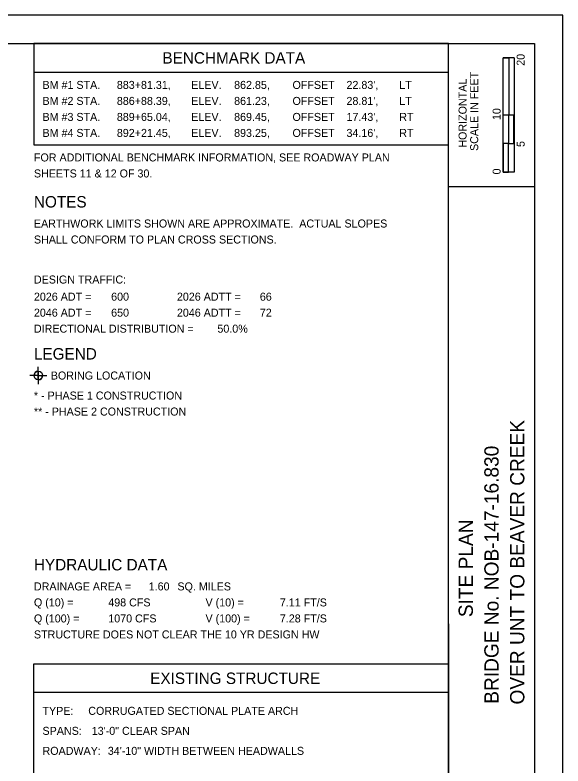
# Model space of a CAD drawing. Extents: x 0 to 2765, y 0 to 220.
# Drawn here: x 244.2 to 340, y 88.6 to 220 of the extents above; entities that cross this region are included whole.
import ezdxf

# ---------------------------------------------------------------- set-up
doc = ezdxf.new("R2010")
doc.units = 0
for name, color, linetype in [('DR_X_Culvert', 7, 'Continuous'), ('PF_P_Grade_Line', 7, 'Continuous'), ('PF_X_Ground_Line', 7, 'Continuous'), ('TX_P_1', 7, 'Continuous')]:
    doc.layers.add(name, color=color, linetype=linetype)

msp = doc.modelspace()

# ---------------------------------------------------------------- linework, layer by layer
at = {"layer": 'DR_X_Culvert'}
msp.add_lwpolyline([(0, 0), (340, 0), (340, 220), (0, 220)], close=True, dxfattribs=at)
at = {"layer": 'PF_P_Grade_Line'}
for p, q in [((248.27, 156.93), (248.27, 158.43)), ((248.27, 157.68), (248.27, 156.93)), ((248.27, 156.93), (246.77, 156.93)), ((248.27, 156.93), (247.52, 156.93)), ((248.27, 156.93), (248.27, 155.43)), ((248.27, 156.93), (249.77, 156.93)), ((248.27, 156.18), (248.27, 156.93)), ((248.27, 156.93), (249.02, 156.93))]:
    msp.add_line(p, q, dxfattribs=at)
msp.add_circle((248.27, 156.93), 0.75, dxfattribs=at)
for start, end in [(90, 180), (270, 360)]:
    msp.add_arc((248.27, 156.93), 0.75, start, end, dxfattribs=at)
at = {"layer": 'PF_X_Ground_Line'}
for p, q in [((320, 5), (320, 215)), ((320, 190), (335, 190))]:
    msp.add_line(p, q, dxfattribs=at)
msp.add_lwpolyline([(15, 215), (335, 215), (335, 5), (15, 5)], close=True, dxfattribs=at)
at = {"layer": 'TX_P_1'}
for p, q in [((329.57, 202.5), (329.57, 212.5)), ((329.57, 212.5), (330.5, 212.5)), ((329.57, 192.5), (329.57, 212.5)), ((331.44, 212.5), (329.57, 212.5)), ((330.5, 212.5), (330.51, 212.5)), ((330.51, 212.5), (330.51, 202.5)), ((331.44, 212.5), (331.44, 192.5)), ((247.5, 210), (320, 210)), ((330.51, 202.5), (329.57, 202.5)), ((331.43, 202.5), (330.5, 202.5)), ((330.5, 202.5), (330.5, 197.5)), ((331.43, 197.5), (331.43, 202.5)), ((330.5, 197.5), (329.57, 197.5)), ((329.57, 197.5), (329.57, 192.5)), ((330.5, 197.5), (331.43, 197.5)), ((330.5, 192.5), (330.5, 197.5)), ((331.44, 192.5), (329.57, 192.5)), ((329.57, 192.5), (330.5, 192.5)), ((320, 113.45), (320, 57.31)), ((247.5, 106.45), (320, 106.45)), ((247.5, 57.31), (247.5, 106.45)), ((320, 101.45), (247.5, 101.45))]:
    msp.add_line(p, q, dxfattribs=at)
msp.add_lwpolyline([(320, 215), (247.5, 215), (247.5, 197.27), (320, 197.27)], close=True, dxfattribs=at)

# ---------------------------------------------------------------- texts
for s, height, p in [('BENCHMARK DATA', 2, (269.97, 211.5)), ('BM #1 STA.', 1.4, (249, 207.07)), ('883+81.31,', 1.4, (262, 207.07)), ('ELEV.', 1.4, (275, 207.07)), ('862.85,', 1.4, (282.5, 207.07)), ('OFFSET', 1.4, (292.71, 207.07)), ("22.83',", 1.4, (302.15, 207.07)), ('LT', 1.4, (311.38, 207.07)), ('BM #2 STA.', 1.4, (249, 204.27)), ('886+88.39,', 1.4, (262, 204.27)), ('ELEV.', 1.4, (275, 204.27)), ('861.23,', 1.4, (282.5, 204.27)), ('OFFSET', 1.4, (292.71, 204.27)), ("28.81',", 1.4, (302.15, 204.27)), ('LT', 1.4, (311.38, 204.27)), ('BM #3 STA.', 1.4, (249, 201.47)), ('889+65.04,', 1.4, (262, 201.47)), ('ELEV.', 1.4, (275, 201.47)), ('869.45,', 1.4, (282.5, 201.47)), ('OFFSET', 1.4, (292.71, 201.47)), ("17.43',", 1.4, (302.15, 201.47)), ('RT', 1.4, (311.38, 201.47)), ('BM #4 STA.', 1.4, (249, 198.67)), ('892+21.45,', 1.4, (262, 198.67)), ('ELEV.', 1.4, (275, 198.67)), ('893.25,', 1.4, (282.5, 198.67)), ('OFFSET', 1.4, (292.71, 198.67)), ("34.16',", 1.4, (302.15, 198.67)), ('RT', 1.4, (311.38, 198.67)), ('FOR ADDITIONAL BENCHMARK INFORMATION, SEE ROADWAY PLAN', 1.4, (247.5, 194.38)), ('SHEETS 11 & 12 OF 30.', 1.4, (247.5, 191.58)), ('NOTES', 2, (247.5, 186.32)), ('EARTHWORK LIMITS SHOWN ARE APPROXIMATE.  ACTUAL SLOPES', 1.4, (247.5, 182.82)), ('SHALL CONFORM TO PLAN CROSS SECTIONS.', 1.4, (247.5, 180.02)), ('DESIGN TRAFFIC:', 1.4, (247.5, 173.02)), ('2026 ADT =', 1.4, (247.5, 170.02)), ('600', 1.4, (261, 170.02)), ('2026 ADTT =', 1.4, (272.5, 170.02)), ('66', 1.4, (287, 170.02)), ('2046 ADT =', 1.4, (247.5, 167.22)), ('650', 1.4, (261, 167.22)), ('2046 ADTT =', 1.4, (272.5, 167.22)), ('72', 1.4, (287, 167.22)), ('DIRECTIONAL DISTRIBUTION =', 1.4, (247.5, 164.42)), ('50.0%', 1.4, (279.58, 164.42)), ('LEGEND', 2, (247.5, 159.72)), ('BORING LOCATION', 1.4, (250.45, 156.22)), ('* - PHASE 1 CONSTRUCTION', 1.4, (247.5, 152.72)), ('** - PHASE 2 CONSTRUCTION', 1.4, (247.5, 149.92)), ('HYDRAULIC DATA', 2, (247.5, 122.82)), ('DRAINAGE AREA =', 1.4, (247.5, 119.32)), ('1.60', 1.4, (267.57, 119.32)), ('SQ. MILES', 1.4, (272.59, 119.32)), ('Q (10) =', 1.4, (247.5, 116.52)), ('498 CFS', 1.4, (260.5, 116.52)), ('V (10) =', 1.4, (277.5, 116.52)), ('7.11 FT/S', 1.4, (290.5, 116.52)), ('Q (100) =', 1.4, (247.5, 113.72)), ('1070 CFS', 1.4, (260.5, 113.72)), ('V (100) =', 1.4, (277.5, 113.72)), ('7.28 FT/S', 1.4, (290.5, 113.72)), ('STRUCTURE DOES NOT CLEAR THE 10 YR DESIGN HW', 1.4, (247.5, 110.92)), ('EXISTING STRUCTURE', 2, (267.83, 102.95)), ('TYPE:', 1.4, (249, 97.55)), ('CORRUGATED SECTIONAL PLATE ARCH', 1.4, (257, 97.55)), ('SPANS:', 1.4, (249, 94.05)), ('13\'-0" CLEAR SPAN', 1.4, (257.61, 94.05)), ('ROADWAY:', 1.4, (249, 90.55)), ('34\'-10" WIDTH BETWEEN HEADWALLS', 1.4, (260.42, 90.55))]:
    msp.add_text(s, height=height, dxfattribs=at).set_placement(p)
for s, height, p in [('20', 1.4, (333.3, 211.12)), ('SCALE IN FEET', 1.4, (325.18, 196.21)), ('HORIZONTAL', 1.4, (323.15, 196.79)), ('10', 1.4, (329.1, 201.62)), ('5', 1.4, (333.3, 196.91)), ('0', 1.4, (329.1, 192.11)), ('OVER UNT TO BEAVER CREEK', 2.5, (333.25, 99.36)), ('BRIDGE No. NOB-147-16.830', 2.5, (328.75, 99.49)), ('SITE PLAN', 2.5, (324.25, 114.64))]:
    msp.add_text(s, height=height, rotation=90, dxfattribs=at).set_placement(p)

doc.saveas('drawing.dxf')
